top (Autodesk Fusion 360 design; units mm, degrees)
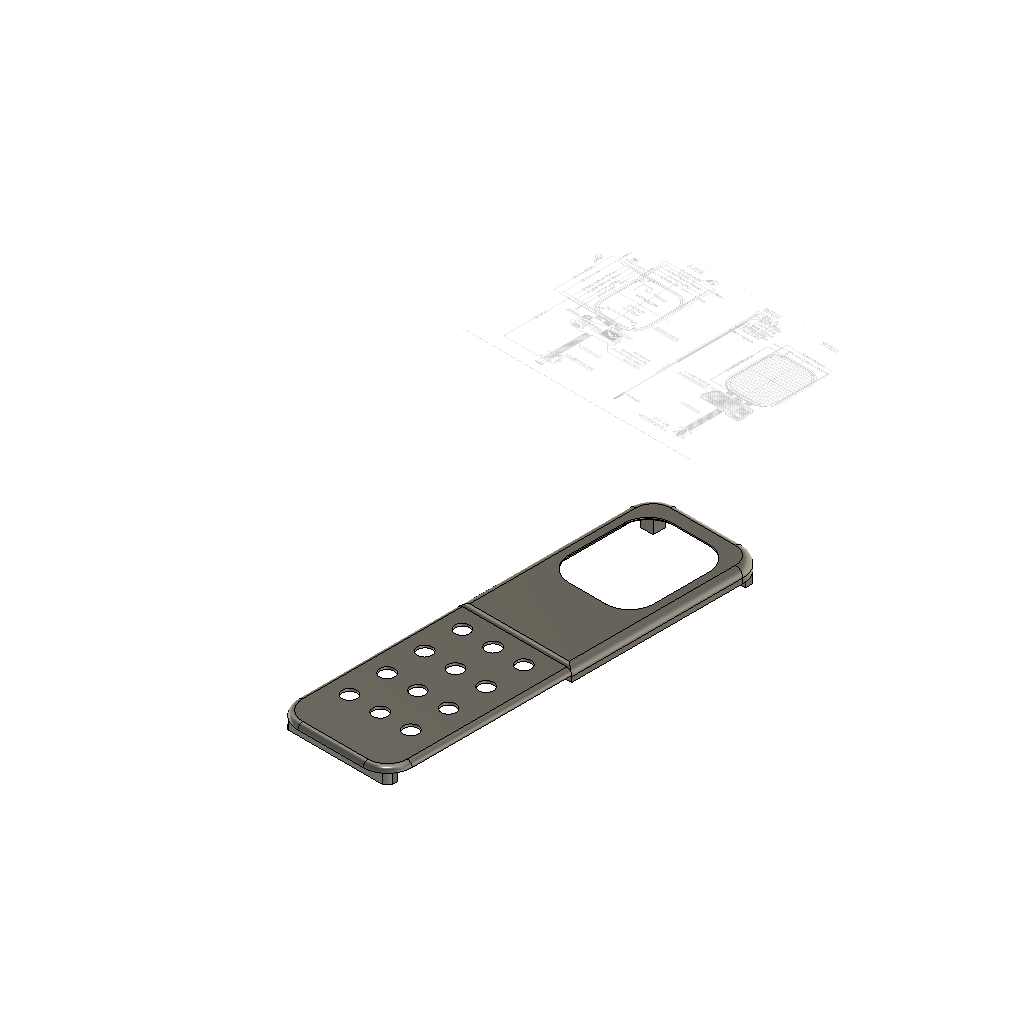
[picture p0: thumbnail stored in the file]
part number: 2026-08-16-12-09-25-921
canvas "Canvas1"
sketch "Sketch1" plane through (0, 0, 0) normal (0, 0, 1) x axis (1, 0, 0)
  line L1 (42.5, 0) -> (0, 0)
  line L2 (0, -72.5) -> (0, -150.5)
  line L3 (-2, 2) -> (-2, -152.5)
  line L4 (-2, -152.5) -> (44.5, -152.5)
  line L5 (42.5, -150.5) -> (42.5, 0)
  line L6 (-2, -61.5) -> (0, -61.5)
  line L7 (0, -150.5) -> (42.5, -150.5)
  line L8 (44.5, -152.5) -> (44.5, 2)
  line L9 (0, -61.5) -> (0, 0)
  line L10 (0, -146.5) -> (42.5, -146.5)
  line L11 (44.5, 2) -> (-2, 2)
  line L12 (-2, -72.5) -> (0, -72.5)
  line L13 (0, 0) -> (0, -150.5)
  line L14 (5, 0) -> (0, 0)
  line L15 (5, -5) -> (5, 0)
  line L16 (0, -5) -> (5, -5)
  line L17 (0, 0) -> (0, -5)
  line L18 (37.5, 0) -> (42.5, 0)
  line L19 (37.5, -5) -> (37.5, 0)
  line L20 (42.5, -5) -> (37.5, -5)
  line L21 (42.5, 0) -> (42.5, -5)
  line L22 (-38.5, -10) -> (-75, -10)
  line L23 (-38.5, -54) -> (-38.5, -10)
  line L24 (-75, -54) -> (-38.5, -54)
  line L25 (-75, -10) -> (-75, -54)
  line L26 (28.71, -49) -> (21.25, -49)
  line L27 (13.79, -49) -> (21.25, -49)
  line L28 (3, -15.79) -> (3, -38.21)
  line L29 (39.5, -15.79) -> (39.5, -38.21)
  line L30 (13.79, -5) -> (28.71, -5)
  line L31 (4, -15.79) -> (4, -38.21)
  line L32 (13.79, -6) -> (28.71, -6)
  line L33 (38.5, -15.79) -> (38.5, -38.21)
  line L34 (28.71, -48) -> (21.25, -48)
  line L35 (13.79, -48) -> (21.25, -48)
  line L36 (8, -150.5) -> (0, -150.5)
  line L37 (8, -131.5) -> (8, -150.5)
  line L38 (0, -131.5) -> (8, -131.5)
  line L39 (0, -150.5) -> (0, -131.5)
  line L40 (20.5, -131.5) -> (8, -131.5)
  line L41 (20.5, -150.5) -> (20.5, -131.5)
  line L42 (8, -150.5) -> (20.5, -150.5)
  line L43 (8, -131.5) -> (8, -150.5)
  line L44 (33, -131.5) -> (20.5, -131.5)
  line L45 (33, -150.5) -> (33, -131.5)
  line L46 (20.5, -150.5) -> (33, -150.5)
  line L47 (20.5, -131.5) -> (20.5, -150.5)
  line L48 (8, -131.5) -> (0, -131.5)
  line L49 (8, -116.2) -> (8, -131.5)
  line L50 (0, -116.2) -> (8, -116.2)
  line L51 (0, -131.5) -> (0, -116.2)
  line L52 (0, -116.2) -> (8, -116.2)
  line L53 (0, -100.9) -> (0, -116.2)
  line L54 (8, -100.9) -> (0, -100.9)
  line L55 (8, -116.2) -> (8, -100.9)
  line L56 (0, -100.9) -> (8, -100.9)
  line L57 (0, -85.6) -> (0, -100.9)
  line L58 (8, -85.6) -> (0, -85.6)
  line L59 (8, -100.9) -> (8, -85.6)
  line L60 (20.5, -116.2) -> (8, -116.2)
  line L61 (20.5, -131.5) -> (20.5, -116.2)
  line L62 (8, -131.5) -> (20.5, -131.5)
  line L63 (8, -116.2) -> (8, -131.5)
  line L64 (33, -116.2) -> (20.5, -116.2)
  line L65 (33, -131.5) -> (33, -116.2)
  line L66 (20.5, -131.5) -> (33, -131.5)
  line L67 (20.5, -116.2) -> (20.5, -131.5)
  line L68 (20.5, -100.9) -> (8, -100.9)
  line L69 (20.5, -116.2) -> (20.5, -100.9)
  line L70 (8, -116.2) -> (20.5, -116.2)
  line L71 (8, -100.9) -> (8, -116.2)
  line L72 (33, -100.9) -> (20.5, -100.9)
  line L73 (33, -116.2) -> (33, -100.9)
  line L74 (20.5, -116.2) -> (33, -116.2)
  line L75 (20.5, -100.9) -> (20.5, -116.2)
  line L76 (20.5, -85.6) -> (8, -85.6)
  line L77 (20.5, -100.9) -> (20.5, -85.6)
  line L78 (8, -100.9) -> (20.5, -100.9)
  line L79 (8, -85.6) -> (8, -100.9)
  line L80 (33, -85.6) -> (20.5, -85.6)
  line L81 (33, -100.9) -> (33, -85.6)
  line L82 (20.5, -100.9) -> (33, -100.9)
  line L83 (20.5, -85.6) -> (20.5, -100.9)
  line L84 (0, -77.6) -> (0, -85.6)
  line L85 (42.5, -77.6) -> (0, -77.6)
  line L86 (44.5, -77.6) -> (42.5, -77.6)
  line L87 (-2, -77.6) -> (0, -77.6)
  line L88 (-2, -75.6) -> (-2, -77.6)
  line L89 (44.5, -75.6) -> (-2, -75.6)
  line L90 (44.5, -75.6) -> (-2, -75.6)
  line L91 (42.5, -79.6) -> (0, -79.6)
  arc A1 centre (13.79, -15.79) radius 10.79 clockwise from (3, -15.79) to (13.79, -5)
  arc A2 centre (13.79, -38.21) radius 10.79 clockwise from (13.79, -49) to (3, -38.21)
  arc A3 centre (28.71, -15.79) radius 10.79 clockwise from (28.71, -5) to (39.5, -15.79)
  arc A4 centre (28.71, -38.21) radius 10.79 clockwise from (39.5, -38.21) to (28.71, -49)
  arc A5 centre (13.79, -15.79) radius 9.79 clockwise from (4, -15.79) to (13.79, -6)
  arc A6 centre (28.71, -15.79) radius 9.79 clockwise from (28.71, -6) to (38.5, -15.79)
  arc A7 centre (28.71, -38.21) radius 9.79 clockwise from (38.5, -38.21) to (28.71, -48)
  arc A8 centre (13.79, -38.21) radius 9.79 clockwise from (13.79, -48) to (4, -38.21)
  circle C1 centre (8, -85.6) radius 3
  circle C2 centre (20.5, -85.6) radius 3
  circle C3 centre (33, -85.6) radius 3
  circle C4 centre (8, -100.9) radius 3
  circle C5 centre (20.5, -100.9) radius 3
  circle C6 centre (33, -100.9) radius 3
  circle C7 centre (8, -116.2) radius 3
  circle C8 centre (20.5, -116.2) radius 3
  circle C9 centre (33, -116.2) radius 3
  circle C10 centre (8, -131.5) radius 3
  circle C11 centre (20.5, -131.5) radius 3
  circle C12 centre (33, -131.5) radius 3
  point P9 (0, 0)
  point P11 (0, 0)
  point P3 (-2, -61.5)
  point P10 (-2, -72.5)
  point P29 (3, -5)
  point P28 (3, -49)
  point P72 (8, -85.6)
  point P85 (8, -85.6)
  point P81 (20.5, -85.6)
  point P86 (20.5, -85.6)
  point P83 (33, -85.6)
  point P87 (33, -85.6)
  point P82 (8, -100.9)
  point P88 (8, -100.9)
  point P84 (20.5, -100.9)
  point P89 (20.5, -100.9)
  point P79 (33, -100.9)
  point P90 (33, -100.9)
  point P78 (8, -116.2)
  point P91 (8, -116.2)
  point P80 (20.5, -116.2)
  point P92 (20.5, -116.2)
  point P75 (33, -116.2)
  point P93 (33, -116.2)
  point P74 (8, -131.5)
  point P94 (8, -131.5)
  point P58 (20.5, -131.5)
  point P95 (20.5, -131.5)
  point P61 (33, -131.5)
  point P96 (33, -131.5)
  point P98 (42.5, -77.6)
  point P99 (44.5, -77.6)
  point P100 (-2, -77.6)
  point P102 (44.5, -75.6)
  point P8 (42.5, 0)
  point P13 (0, -150.5)
  point P16 (0, -61.5)
  point P2 (0, -72.5)
  point P17 (5, 0)
  point P19 (0, -5)
  point P20 (37.5, 0)
  point P22 (42.5, -5)
  point P23 (-75, -10)
  point P24 (-38.5, -10)
  point P26 (-75, -54)
  point P57 (0, -131.5)
  point P56 (8, -131.5)
  point P64 (8, -131.5)
  point P66 (0, -116.2)
  point P65 (8, -116.2)
  point P67 (0, -116.2)
  point P69 (8, -100.9)
  point P70 (0, -100.9)
  point P71 (0, -85.6)
  point P97 (0, -77.6)
  point P101 (-2, -75.6)
  horizontal L1
  vertical L5
  horizontal L7
  vertical L13
  coincident P9 P11
  horizontal L10
  perpendicular L2 L10
  coincident P3 L3
  perpendicular L3 L6
  coincident P10 L3
  perpendicular L3 L12
  horizontal L14
  vertical L15
  horizontal L16
  vertical L17
  horizontal L18
  vertical L19
  horizontal L20
  vertical L21
  horizontal L22
  vertical L23
  horizontal L24
  vertical L25
  perpendicular L27 L28
  perpendicular L26 L29
  coincident P29 L28
  coincident P29 L30
  tangent L28 A1
  tangent L30 A1
  coincident P28 L27
  coincident P28 L28
  tangent L27 A2
  tangent L28 A2
  tangent L29 A3
  tangent L30 A3
  tangent L26 A4
  tangent L29 A4
  horizontal L36
  vertical L37
  horizontal L38
  vertical L39
  horizontal L40
  vertical L41
  horizontal L42
  vertical L43
  horizontal L44
  vertical L45
  horizontal L46
  vertical L47
  horizontal L48
  vertical L49
  horizontal L50
  vertical L51
  horizontal L52
  vertical L53
  horizontal L54
  vertical L55
  horizontal L56
  vertical L57
  horizontal L58
  vertical L59
  horizontal L60
  vertical L61
  horizontal L62
  vertical L63
  horizontal L64
  vertical L65
  horizontal L66
  vertical L67
  horizontal L68
  vertical L69
  horizontal L70
  vertical L71
  horizontal L72
  vertical L73
  horizontal L74
  vertical L75
  horizontal L76
  vertical L77
  horizontal L78
  vertical L79
  horizontal L80
  vertical L81
  horizontal L82
  vertical L83
  coincident P72 P85
  coincident P81 P86
  coincident P83 P87
  coincident P82 P88
  coincident P84 P89
  coincident P79 P90
  coincident P78 P91
  coincident P80 P92
  coincident P75 P93
  coincident P74 P94
  coincident P58 P95
  coincident P61 P96
  perpendicular L58 L84
  coincident L5 P98
  perpendicular L5 L85
  coincident L8 P99
  perpendicular L8 L86
  coincident L3 P100
  perpendicular L3 L87
  perpendicular L12 L88
  coincident L8 P102
  perpendicular L8 L89
  dimension "d2" = -2
  dimension "d3" distance P8 P9 = 42.5
  dimension "d4" distance P9 P13 = 150.5
  dimension "d14" distance P9 P16 = 61.5
  dimension "d15" distance P2 P13 = 78
  dimension "d16" distance P9 P17 = 5
  dimension "d17" distance P9 P19 = 5
  dimension "d18" distance P8 P20 = 5
  dimension "d19" distance P8 P22 = 5
  dimension "d20" distance P23 P24 = 36.5
  dimension "d21" distance P23 P26 = 44
  dimension "d25" distance P28 P29 = 44
  dimension "d27" radius A1 = 10.79
  dimension "d28" radius A2 = 10.79
  dimension "d29" radius A3 = 10.79
  dimension "d30" radius A4 = 10.79
  dimension "d31" = -1
  dimension "d32" distance P13 P57 = 19
  dimension "d33" distance P56 P58 = 12.5
  dimension "d35" distance P58 P61 = 12.5
  dimension "d38" distance L13 L37 = 8
  dimension "d39" distance P57 P64 = 8
  dimension "d40" distance P57 P66 = 15.3
  dimension "d41" distance P65 P67 = 8
  dimension "d42" distance P65 P69 = 15.3
  dimension "d43" distance P69 P70 = 8
  dimension "d44" distance P69 P72 = 15.3
  dimension "d45" distance L36 L58 = 64.9
  dimension "d47" diameter C1 = 6
  dimension "d48" diameter C2 = 6
  dimension "d49" diameter C3 = 6
  dimension "d50" diameter C4 = 6
  dimension "d51" diameter C5 = 6
  dimension "d52" diameter C6 = 6
  dimension "d53" diameter C7 = 6
  dimension "d54" diameter C8 = 6
  dimension "d55" diameter C9 = 6
  dimension "d56" diameter C10 = 6
  dimension "d57" diameter C11 = 6
  dimension "d58" diameter C12 = 6
  dimension "d61" distance P71 P97 = 8
  dimension "d68" distance P100 P101 = 2
extrude "Extrude1" new body sketch "Sketch1" profile of L2 L5 L7 L10 L13 L8 L4 L3 L36 L37 L38 L39 L40 L41 L42 L43 L44 L45 L46 L47 L48 L49 L50 L51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 along normal blind 1
extrude "Extrude2" add sketch "Sketch1" profile of L2 L5 L7 L13 L8 L4 L3 L36 L39 L42 L46 L51 L53 L57 L84 L85 L86 L87 L91 against normal blind 1
extrude "Extrude3" add sketch "Sketch1" profile of L2 L5 L7 L10 L13 L36 L37 L39 L41 L42 L43 L45 L46 L47 against normal blind 5
extrude "Extrude4" new body sketch "Sketch1" profile of L1 L2 L5 L6 L9 L12 L13 L11 L8 L3 L14 L17 L18 L21 L86 L87 L88 L89 against normal blind 3.5
extrude "Extrude5" add sketch "Sketch1" profile of L1 L5 L9 L13 L14 L15 L16 L17 L18 L19 L20 L21 against normal blind 7.5
extrude "Extrude7" add sketch "Sketch1" profile of L2 L5 L13 L85 L89 L90 against normal blind 3.5
extrude "Extrude6" add sketch "Sketch1" profile of L1 L2 L5 L6 L9 L12 L13 L11 L8 L3 L14 L15 L16 L17 L18 L19 L20 L21 L26 L27 L28 L29 L30 A1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 along normal blind 1.5
extrude "Extrude8" add sketch "Sketch1" profile of L26 L27 L28 L29 L30 A1 A2 A3 A4 A5 L31 A6 L32 L35 L34 L33 A7 A8 along normal blind 1.5
extrude "Extrude9" cut sketch "Sketch1" profile of L26 L27 L28 L29 L30 A1 A2 A3 A4 A5 L31 A6 L32 L35 L34 L33 A7 A8 along normal blind 1
fillet "Fillet1" radius 10
fillet "Fillet3" radius 2
fillet "Fillet5" radius 3
fillet "Fillet6" radius 2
